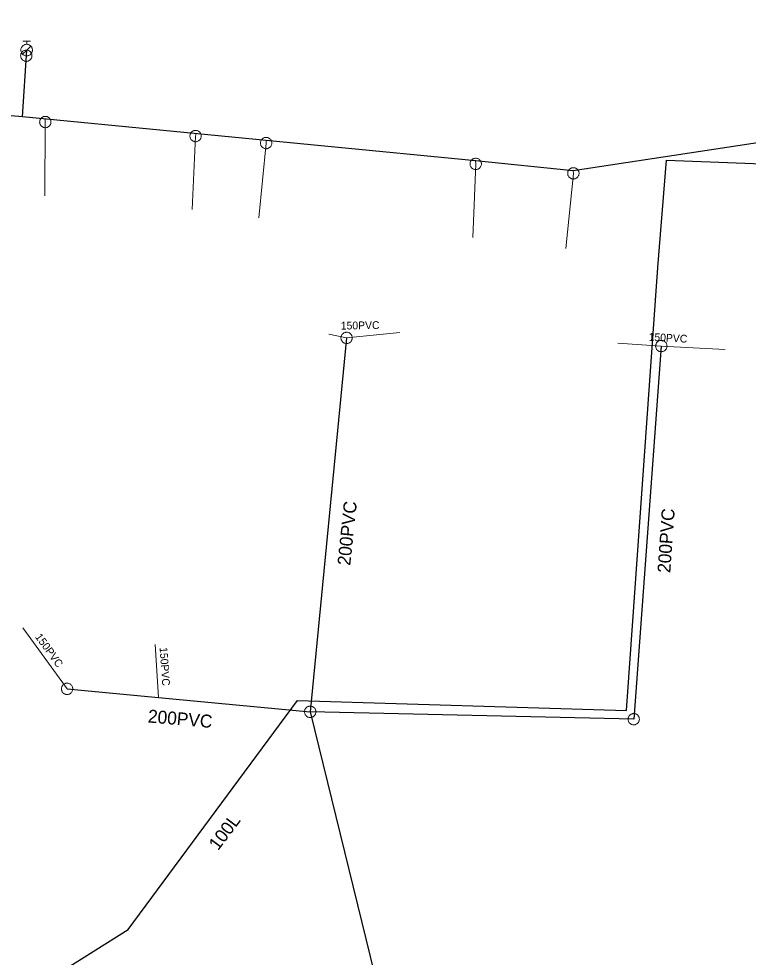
# Model space of a CAD drawing. Extents: x -741806 to -738704, y -1059275 to -1055387.
# Drawn here: x -740724.1 to -740667.8, y -1057649.4 to -1057576.9 of the extents above; entities that cross this region are included whole.
import ezdxf

# ---------------------------------------------------------------- set-up
doc = ezdxf.new("R2010")
doc.units = 0
doc.header["$LTSCALE"] = 0.4
for name, color, linetype, lineweight in [('2', 7, 'Continuous', 25), ('21', 7, 'Continuous', 13), ('3', 7, 'Continuous', 13), ('50', 7, 'Continuous', 13), ('51', 7, 'Continuous', 13), ('52', 7, 'Continuous', 25), ('56', 7, 'Continuous', 13)]:
    doc.layers.add(name, color=color, linetype=linetype, lineweight=lineweight)
doc.layers.add('5', color=7, linetype='Continuous')
doc.layers.add('55', color=7, linetype='Continuous')

msp = doc.modelspace()

# ---------------------------------------------------------------- linework, layer by layer
at = {"layer": '2'}
msp.add_line((-740698.8, -1057601.58), (-740701.609, -1057630.44), dxfattribs=at)
for points in [[(-740702.59, -1057629.575), (-740677.195, -1057630.344), (-740674.756, -1057596.152), (-740674.105, -1057587.855), (-740634.449, -1057589.387), (-740633.142, -1057565.869)], [(-740674.5, -1057602.21), (-740676.629, -1057631.01), (-740701.609, -1057630.44)], [(-740720.379, -1057628.669), (-740713.316, -1057629.345), (-740701.609, -1057630.44)], [(-740723.35, -1057652.071), (-740715.67, -1057647.25), (-740702.59, -1057629.575)], [(-740701.609, -1057630.44), (-740690.68, -1057675.03), (-740701.17, -1057709.36)]]:
    msp.add_lwpolyline(points, dxfattribs=at)
at = {"layer": '21'}
for points in [[(-740722.077, -1057584.688), (-740722.059, -1057584.919), (-740722.101, -1057590.605)], [(-740710.424, -1057585.816), (-740710.46, -1057586), (-740710.73, -1057591.678)], [(-740705.013, -1057586.34), (-740705.01, -1057586.54), (-740705.581, -1057592.321)], [(-740688.844, -1057587.905), (-740688.829, -1057588.149), (-740689.061, -1057593.823)], [(-740681.293, -1057588.681), (-740681.289, -1057588.879), (-740681.875, -1057594.681)]]:
    msp.add_lwpolyline(points, dxfattribs=at)
at = {"layer": '3'}
for points in [[(-740698.371, -1057601.669), (-740698.365, -1057601.624), (-740698.362, -1057601.579), (-740698.365, -1057601.532), (-740698.372, -1057601.488), (-740698.384, -1057601.444), (-740698.401, -1057601.4), (-740698.422, -1057601.36), (-740698.447, -1057601.321), (-740698.476, -1057601.287), (-740698.508, -1057601.254), (-740698.544, -1057601.226), (-740698.583, -1057601.2), (-740698.624, -1057601.18), (-740698.666, -1057601.163), (-740698.711, -1057601.152), (-740698.756, -1057601.145), (-740698.802, -1057601.143), (-740698.847, -1057601.145), (-740698.893, -1057601.153), (-740698.937, -1057601.165), (-740698.979, -1057601.182), (-740699.019, -1057601.202), (-740699.058, -1057601.228), (-740699.094, -1057601.256), (-740699.126, -1057601.289), (-740699.154, -1057601.326), (-740699.179, -1057601.363), (-740699.2, -1057601.405), (-740699.216, -1057601.447), (-740699.228, -1057601.492), (-740699.235, -1057601.537), (-740699.237, -1057601.582), (-740699.235, -1057601.629), (-740699.227, -1057601.674), (-740699.215, -1057601.717), (-740699.199, -1057601.761), (-740699.177, -1057601.801), (-740699.152, -1057601.84), (-740699.123, -1057601.874), (-740699.091, -1057601.907), (-740699.055, -1057601.935), (-740699.017, -1057601.961), (-740698.976, -1057601.982), (-740698.933, -1057601.998), (-740698.889, -1057602.009), (-740698.843, -1057602.016), (-740698.798, -1057602.019), (-740698.752, -1057602.016), (-740698.707, -1057602.008), (-740698.662, -1057601.996), (-740698.62, -1057601.979), (-740698.579, -1057601.959), (-740698.541, -1057601.933), (-740698.505, -1057601.905), (-740698.473, -1057601.871), (-740698.444, -1057601.836), (-740698.42, -1057601.798), (-740698.399, -1057601.756), (-740698.383, -1057601.714), (-740698.371, -1057601.67)], [(-740674.937, -1057602.187), (-740674.936, -1057602.232), (-740674.932, -1057602.277), (-740674.922, -1057602.322), (-740674.908, -1057602.365), (-740674.889, -1057602.407), (-740674.866, -1057602.447), (-740674.839, -1057602.484), (-740674.809, -1057602.519), (-740674.774, -1057602.548), (-740674.738, -1057602.575), (-740674.698, -1057602.598), (-740674.656, -1057602.618), (-740674.612, -1057602.631), (-740674.568, -1057602.641), (-740674.522, -1057602.645), (-740674.476, -1057602.646), (-740674.431, -1057602.64), (-740674.386, -1057602.631), (-740674.342, -1057602.617), (-740674.3, -1057602.598), (-740674.261, -1057602.575), (-740674.225, -1057602.549), (-740674.19, -1057602.517), (-740674.159, -1057602.484), (-740674.132, -1057602.446), (-740674.11, -1057602.406), (-740674.091, -1057602.365), (-740674.077, -1057602.321), (-740674.067, -1057602.276), (-740674.063, -1057602.23), (-740674.063, -1057602.185), (-740674.067, -1057602.14), (-740674.077, -1057602.095), (-740674.092, -1057602.051), (-740674.11, -1057602.01), (-740674.133, -1057601.97), (-740674.16, -1057601.933), (-740674.191, -1057601.898), (-740674.225, -1057601.869), (-740674.261, -1057601.842), (-740674.301, -1057601.819), (-740674.343, -1057601.799), (-740674.387, -1057601.785), (-740674.431, -1057601.776), (-740674.477, -1057601.772), (-740674.523, -1057601.771), (-740674.568, -1057601.776), (-740674.613, -1057601.786), (-740674.657, -1057601.8), (-740674.699, -1057601.819), (-740674.738, -1057601.842), (-740674.775, -1057601.868), (-740674.809, -1057601.9), (-740674.84, -1057601.933), (-740674.867, -1057601.971), (-740674.89, -1057602.011), (-740674.908, -1057602.052), (-740674.922, -1057602.096), (-740674.932, -1057602.141), (-740674.937, -1057602.186)], [(-740720.122, -1057629.023), (-740720.087, -1057628.994), (-740720.055, -1057628.962), (-740720.025, -1057628.926), (-740720.001, -1057628.888), (-740719.98, -1057628.847), (-740719.963, -1057628.804), (-740719.952, -1057628.76), (-740719.944, -1057628.715), (-740719.942, -1057628.669), (-740719.944, -1057628.624), (-740719.951, -1057628.578), (-740719.963, -1057628.534), (-740719.98, -1057628.492), (-740720, -1057628.45), (-740720.025, -1057628.412), (-740720.054, -1057628.376), (-740720.087, -1057628.344), (-740720.122, -1057628.315), (-740720.161, -1057628.29), (-740720.202, -1057628.269), (-740720.244, -1057628.253), (-740720.287, -1057628.242), (-740720.334, -1057628.234), (-740720.379, -1057628.231), (-740720.425, -1057628.234), (-740720.47, -1057628.242), (-740720.514, -1057628.253), (-740720.558, -1057628.27), (-740720.598, -1057628.29), (-740720.636, -1057628.316), (-740720.672, -1057628.344), (-740720.704, -1057628.376), (-740720.733, -1057628.412), (-740720.758, -1057628.451), (-740720.779, -1057628.491), (-740720.796, -1057628.534), (-740720.807, -1057628.578), (-740720.814, -1057628.624), (-740720.816, -1057628.669), (-740720.814, -1057628.714), (-740720.807, -1057628.76), (-740720.796, -1057628.805), (-740720.78, -1057628.847), (-740720.759, -1057628.888), (-740720.733, -1057628.926), (-740720.705, -1057628.962), (-740720.673, -1057628.994), (-740720.637, -1057629.023), (-740720.598, -1057629.048), (-740720.557, -1057629.069), (-740720.514, -1057629.085), (-740720.471, -1057629.097), (-740720.425, -1057629.104), (-740720.38, -1057629.107), (-740720.333, -1057629.104), (-740720.288, -1057629.097), (-740720.245, -1057629.085), (-740720.201, -1057629.069), (-740720.161, -1057629.048), (-740720.122, -1057629.024)], [(-740701.172, -1057630.481), (-740701.171, -1057630.436), (-740701.174, -1057630.39), (-740701.182, -1057630.344), (-740701.194, -1057630.301), (-740701.211, -1057630.258), (-740701.232, -1057630.217), (-740701.258, -1057630.18), (-740701.287, -1057630.144), (-740701.32, -1057630.112), (-740701.355, -1057630.084), (-740701.394, -1057630.059), (-740701.435, -1057630.038), (-740701.478, -1057630.023), (-740701.522, -1057630.011), (-740701.568, -1057630.005), (-740701.614, -1057630.003), (-740701.659, -1057630.006), (-740701.704, -1057630.013), (-740701.749, -1057630.026), (-740701.791, -1057630.043), (-740701.832, -1057630.065), (-740701.869, -1057630.089), (-740701.905, -1057630.119), (-740701.937, -1057630.151), (-740701.966, -1057630.188), (-740701.989, -1057630.227), (-740702.01, -1057630.267), (-740702.026, -1057630.311), (-740702.037, -1057630.355), (-740702.044, -1057630.4), (-740702.046, -1057630.445), (-740702.043, -1057630.491), (-740702.035, -1057630.537), (-740702.022, -1057630.581), (-740702.006, -1057630.623), (-740701.985, -1057630.664), (-740701.959, -1057630.701), (-740701.93, -1057630.737), (-740701.897, -1057630.769), (-740701.862, -1057630.797), (-740701.823, -1057630.822), (-740701.782, -1057630.843), (-740701.739, -1057630.859), (-740701.695, -1057630.87), (-740701.649, -1057630.876), (-740701.603, -1057630.878), (-740701.558, -1057630.876), (-740701.513, -1057630.868), (-740701.469, -1057630.855), (-740701.426, -1057630.838), (-740701.386, -1057630.816), (-740701.347, -1057630.792), (-740701.312, -1057630.762), (-740701.28, -1057630.73), (-740701.252, -1057630.693), (-740701.227, -1057630.654), (-740701.207, -1057630.614), (-740701.191, -1057630.57), (-740701.18, -1057630.526), (-740701.173, -1057630.482)], [(-740676.661, -1057631.446), (-740676.616, -1057631.447), (-740676.571, -1057631.443), (-740676.525, -1057631.434), (-740676.482, -1057631.421), (-740676.44, -1057631.404), (-740676.399, -1057631.381), (-740676.362, -1057631.355), (-740676.326, -1057631.326), (-740676.296, -1057631.292), (-740676.268, -1057631.256), (-740676.244, -1057631.216), (-740676.224, -1057631.175), (-740676.21, -1057631.132), (-740676.199, -1057631.087), (-740676.193, -1057631.042), (-740676.192, -1057630.996), (-740676.196, -1057630.95), (-740676.204, -1057630.906), (-740676.218, -1057630.861), (-740676.236, -1057630.819), (-740676.258, -1057630.779), (-740676.283, -1057630.742), (-740676.314, -1057630.707), (-740676.347, -1057630.675), (-740676.384, -1057630.648), (-740676.423, -1057630.625), (-740676.464, -1057630.605), (-740676.508, -1057630.589), (-740676.552, -1057630.579), (-740676.598, -1057630.574), (-740676.643, -1057630.572), (-740676.688, -1057630.576), (-740676.734, -1057630.585), (-740676.778, -1057630.598), (-740676.819, -1057630.615), (-740676.86, -1057630.637), (-740676.897, -1057630.664), (-740676.933, -1057630.694), (-740676.963, -1057630.727), (-740676.991, -1057630.763), (-740677.015, -1057630.802), (-740677.035, -1057630.844), (-740677.05, -1057630.887), (-740677.06, -1057630.931), (-740677.066, -1057630.977), (-740677.067, -1057631.023), (-740677.064, -1057631.069), (-740677.055, -1057631.113), (-740677.041, -1057631.157), (-740677.023, -1057631.2), (-740677.001, -1057631.24), (-740676.976, -1057631.278), (-740676.945, -1057631.312), (-740676.912, -1057631.343), (-740676.875, -1057631.371), (-740676.836, -1057631.395), (-740676.795, -1057631.414), (-740676.751, -1057631.43), (-740676.707, -1057631.44), (-740676.662, -1057631.446)]]:
    msp.add_lwpolyline(points, dxfattribs=at)
at = {"layer": '50'}
for p, q in [((-740723.808, -1057578.666), (-740723.5, -1057578.666)), ((-740723.5, -1057578.917), (-740723.5, -1057578.666)), ((-740723.193, -1057578.666), (-740723.5, -1057578.666)), ((-740723.5, -1057579.364), (-740723.817, -1057579.681)), ((-740723.5, -1057579.364), (-740723.184, -1057579.052))]:
    msp.add_line(p, q, dxfattribs=at)
msp.add_lwpolyline([(-740723.056, -1057579.368), (-740723.058, -1057579.319), (-740723.063, -1057579.273), (-740723.076, -1057579.227), (-740723.093, -1057579.184), (-740723.112, -1057579.144), (-740723.139, -1057579.103), (-740723.168, -1057579.068), (-740723.201, -1057579.033), (-740723.236, -1057579.003), (-740723.276, -1057578.979), (-740723.317, -1057578.957), (-740723.36, -1057578.938), (-740723.406, -1057578.928), (-740723.452, -1057578.92), (-740723.498, -1057578.917), (-740723.544, -1057578.92), (-740723.589, -1057578.925), (-740723.635, -1057578.938), (-740723.679, -1057578.955), (-740723.722, -1057578.976), (-740723.76, -1057579.001), (-740723.797, -1057579.03), (-740723.83, -1057579.063), (-740723.859, -1057579.098), (-740723.886, -1057579.138), (-740723.908, -1057579.179), (-740723.924, -1057579.222), (-740723.938, -1057579.268), (-740723.943, -1057579.314), (-740723.95, -1057579.36), (-740723.947, -1057579.408), (-740723.939, -1057579.454), (-740723.928, -1057579.497), (-740723.912, -1057579.543), (-740723.89, -1057579.584), (-740723.866, -1057579.624), (-740723.836, -1057579.659), (-740723.804, -1057579.694), (-740723.766, -1057579.724), (-740723.728, -1057579.748), (-740723.685, -1057579.77), (-740723.642, -1057579.786), (-740723.599, -1057579.8), (-740723.55, -1057579.808), (-740723.504, -1057579.811), (-740723.458, -1057579.808), (-740723.412, -1057579.8), (-740723.366, -1057579.789), (-740723.323, -1057579.773), (-740723.28, -1057579.751), (-740723.242, -1057579.727), (-740723.204, -1057579.697), (-740723.172, -1057579.665), (-740723.142, -1057579.63), (-740723.118, -1057579.589), (-740723.094, -1057579.549), (-740723.077, -1057579.505), (-740723.067, -1057579.46), (-740723.059, -1057579.414)], close=True, dxfattribs=at)
at = {"layer": '51'}
for points in [[(-740723.091, -1057579.802), (-740723.093, -1057579.757), (-740723.1, -1057579.712), (-740723.112, -1057579.667), (-740723.128, -1057579.625), (-740723.149, -1057579.584), (-740723.174, -1057579.545), (-740723.203, -1057579.51), (-740723.235, -1057579.477), (-740723.271, -1057579.449), (-740723.309, -1057579.424), (-740723.35, -1057579.403), (-740723.393, -1057579.386), (-740723.437, -1057579.374), (-740723.482, -1057579.367), (-740723.528, -1057579.365), (-740723.574, -1057579.367), (-740723.619, -1057579.374), (-740723.663, -1057579.386), (-740723.706, -1057579.403), (-740723.747, -1057579.424), (-740723.785, -1057579.449), (-740723.821, -1057579.477), (-740723.853, -1057579.51), (-740723.882, -1057579.545), (-740723.907, -1057579.584), (-740723.928, -1057579.625), (-740723.944, -1057579.667), (-740723.956, -1057579.712), (-740723.963, -1057579.757), (-740723.966, -1057579.803), (-740723.963, -1057579.848), (-740723.956, -1057579.893), (-740723.944, -1057579.938), (-740723.928, -1057579.98), (-740723.907, -1057580.021), (-740723.882, -1057580.06), (-740723.853, -1057580.095), (-740723.821, -1057580.128), (-740723.785, -1057580.156), (-740723.747, -1057580.181), (-740723.706, -1057580.202), (-740723.663, -1057580.219), (-740723.619, -1057580.23), (-740723.574, -1057580.238), (-740723.528, -1057580.24), (-740723.482, -1057580.238), (-740723.437, -1057580.23), (-740723.393, -1057580.219), (-740723.35, -1057580.202), (-740723.309, -1057580.181), (-740723.271, -1057580.156), (-740723.235, -1057580.128), (-740723.203, -1057580.095), (-740723.174, -1057580.06), (-740723.149, -1057580.021), (-740723.128, -1057579.98), (-740723.112, -1057579.938), (-740723.1, -1057579.893), (-740723.093, -1057579.848), (-740723.091, -1057579.803)], [(-740721.622, -1057584.919), (-740721.624, -1057584.874), (-740721.631, -1057584.829), (-740721.643, -1057584.784), (-740721.659, -1057584.742), (-740721.68, -1057584.701), (-740721.705, -1057584.662), (-740721.734, -1057584.627), (-740721.766, -1057584.594), (-740721.802, -1057584.566), (-740721.84, -1057584.541), (-740721.881, -1057584.52), (-740721.924, -1057584.503), (-740721.968, -1057584.491), (-740722.013, -1057584.484), (-740722.059, -1057584.482), (-740722.105, -1057584.484), (-740722.15, -1057584.491), (-740722.194, -1057584.503), (-740722.237, -1057584.52), (-740722.278, -1057584.541), (-740722.316, -1057584.566), (-740722.352, -1057584.594), (-740722.384, -1057584.627), (-740722.413, -1057584.662), (-740722.438, -1057584.701), (-740722.459, -1057584.742), (-740722.475, -1057584.784), (-740722.487, -1057584.829), (-740722.494, -1057584.874), (-740722.497, -1057584.92), (-740722.494, -1057584.965), (-740722.487, -1057585.01), (-740722.475, -1057585.055), (-740722.459, -1057585.097), (-740722.438, -1057585.138), (-740722.413, -1057585.177), (-740722.384, -1057585.212), (-740722.352, -1057585.245), (-740722.316, -1057585.273), (-740722.278, -1057585.298), (-740722.237, -1057585.319), (-740722.194, -1057585.336), (-740722.15, -1057585.347), (-740722.105, -1057585.355), (-740722.059, -1057585.357), (-740722.013, -1057585.355), (-740721.968, -1057585.347), (-740721.924, -1057585.336), (-740721.881, -1057585.319), (-740721.84, -1057585.298), (-740721.802, -1057585.273), (-740721.766, -1057585.245), (-740721.734, -1057585.212), (-740721.705, -1057585.177), (-740721.68, -1057585.138), (-740721.659, -1057585.097), (-740721.643, -1057585.055), (-740721.631, -1057585.01), (-740721.624, -1057584.965), (-740721.622, -1057584.92)], [(-740710.022, -1057586), (-740710.024, -1057585.955), (-740710.032, -1057585.91), (-740710.044, -1057585.865), (-740710.059, -1057585.823), (-740710.081, -1057585.782), (-740710.105, -1057585.743), (-740710.135, -1057585.708), (-740710.167, -1057585.675), (-740710.203, -1057585.647), (-740710.24, -1057585.622), (-740710.282, -1057585.601), (-740710.325, -1057585.584), (-740710.369, -1057585.572), (-740710.414, -1057585.565), (-740710.46, -1057585.563), (-740710.505, -1057585.565), (-740710.551, -1057585.572), (-740710.595, -1057585.584), (-740710.637, -1057585.601), (-740710.679, -1057585.622), (-740710.717, -1057585.647), (-740710.752, -1057585.675), (-740710.784, -1057585.708), (-740710.814, -1057585.743), (-740710.838, -1057585.782), (-740710.86, -1057585.823), (-740710.875, -1057585.865), (-740710.887, -1057585.91), (-740710.895, -1057585.955), (-740710.897, -1057586.001), (-740710.895, -1057586.046), (-740710.887, -1057586.091), (-740710.875, -1057586.136), (-740710.86, -1057586.178), (-740710.838, -1057586.219), (-740710.814, -1057586.258), (-740710.784, -1057586.293), (-740710.752, -1057586.326), (-740710.717, -1057586.354), (-740710.679, -1057586.379), (-740710.637, -1057586.4), (-740710.595, -1057586.417), (-740710.551, -1057586.428), (-740710.505, -1057586.436), (-740710.46, -1057586.438), (-740710.414, -1057586.436), (-740710.369, -1057586.428), (-740710.325, -1057586.417), (-740710.282, -1057586.4), (-740710.24, -1057586.379), (-740710.203, -1057586.354), (-740710.167, -1057586.326), (-740710.135, -1057586.293), (-740710.105, -1057586.258), (-740710.081, -1057586.219), (-740710.059, -1057586.178), (-740710.044, -1057586.136), (-740710.032, -1057586.091), (-740710.024, -1057586.046), (-740710.022, -1057586.001)], [(-740704.573, -1057586.54), (-740704.575, -1057586.495), (-740704.582, -1057586.45), (-740704.594, -1057586.405), (-740704.61, -1057586.363), (-740704.631, -1057586.322), (-740704.656, -1057586.283), (-740704.685, -1057586.248), (-740704.717, -1057586.215), (-740704.753, -1057586.187), (-740704.791, -1057586.162), (-740704.832, -1057586.141), (-740704.875, -1057586.124), (-740704.919, -1057586.112), (-740704.964, -1057586.105), (-740705.01, -1057586.103), (-740705.056, -1057586.105), (-740705.101, -1057586.112), (-740705.145, -1057586.124), (-740705.188, -1057586.141), (-740705.229, -1057586.162), (-740705.267, -1057586.187), (-740705.303, -1057586.215), (-740705.335, -1057586.248), (-740705.364, -1057586.283), (-740705.389, -1057586.322), (-740705.41, -1057586.363), (-740705.426, -1057586.405), (-740705.438, -1057586.45), (-740705.445, -1057586.495), (-740705.448, -1057586.541), (-740705.445, -1057586.586), (-740705.438, -1057586.631), (-740705.426, -1057586.676), (-740705.41, -1057586.718), (-740705.389, -1057586.759), (-740705.364, -1057586.798), (-740705.335, -1057586.833), (-740705.303, -1057586.866), (-740705.267, -1057586.894), (-740705.229, -1057586.919), (-740705.188, -1057586.94), (-740705.145, -1057586.957), (-740705.101, -1057586.968), (-740705.056, -1057586.976), (-740705.01, -1057586.978), (-740704.964, -1057586.976), (-740704.919, -1057586.968), (-740704.875, -1057586.957), (-740704.832, -1057586.94), (-740704.791, -1057586.919), (-740704.753, -1057586.894), (-740704.717, -1057586.866), (-740704.685, -1057586.833), (-740704.656, -1057586.798), (-740704.631, -1057586.759), (-740704.61, -1057586.718), (-740704.594, -1057586.676), (-740704.582, -1057586.631), (-740704.575, -1057586.586), (-740704.573, -1057586.541)], [(-740688.392, -1057588.149), (-740688.394, -1057588.104), (-740688.401, -1057588.059), (-740688.413, -1057588.014), (-740688.429, -1057587.972), (-740688.45, -1057587.931), (-740688.475, -1057587.892), (-740688.504, -1057587.857), (-740688.536, -1057587.824), (-740688.572, -1057587.796), (-740688.61, -1057587.771), (-740688.651, -1057587.75), (-740688.694, -1057587.733), (-740688.738, -1057587.721), (-740688.783, -1057587.714), (-740688.829, -1057587.712), (-740688.875, -1057587.714), (-740688.92, -1057587.721), (-740688.964, -1057587.733), (-740689.007, -1057587.75), (-740689.048, -1057587.771), (-740689.086, -1057587.796), (-740689.122, -1057587.824), (-740689.154, -1057587.857), (-740689.183, -1057587.892), (-740689.208, -1057587.931), (-740689.229, -1057587.972), (-740689.245, -1057588.014), (-740689.257, -1057588.059), (-740689.264, -1057588.104), (-740689.267, -1057588.15), (-740689.264, -1057588.195), (-740689.257, -1057588.24), (-740689.245, -1057588.285), (-740689.229, -1057588.327), (-740689.208, -1057588.368), (-740689.183, -1057588.407), (-740689.154, -1057588.442), (-740689.122, -1057588.475), (-740689.086, -1057588.503), (-740689.048, -1057588.528), (-740689.007, -1057588.549), (-740688.964, -1057588.566), (-740688.92, -1057588.577), (-740688.875, -1057588.585), (-740688.829, -1057588.587), (-740688.783, -1057588.585), (-740688.738, -1057588.577), (-740688.694, -1057588.566), (-740688.651, -1057588.549), (-740688.61, -1057588.528), (-740688.572, -1057588.503), (-740688.536, -1057588.475), (-740688.504, -1057588.442), (-740688.475, -1057588.407), (-740688.45, -1057588.368), (-740688.429, -1057588.327), (-740688.413, -1057588.285), (-740688.401, -1057588.24), (-740688.394, -1057588.195), (-740688.392, -1057588.15)], [(-740680.852, -1057588.879), (-740680.853, -1057588.834), (-740680.861, -1057588.789), (-740680.873, -1057588.744), (-740680.889, -1057588.702), (-740680.91, -1057588.661), (-740680.934, -1057588.622), (-740680.964, -1057588.587), (-740680.996, -1057588.554), (-740681.032, -1057588.526), (-740681.07, -1057588.501), (-740681.111, -1057588.48), (-740681.154, -1057588.463), (-740681.198, -1057588.451), (-740681.243, -1057588.444), (-740681.289, -1057588.442), (-740681.335, -1057588.444), (-740681.38, -1057588.451), (-740681.424, -1057588.463), (-740681.467, -1057588.48), (-740681.508, -1057588.501), (-740681.546, -1057588.526), (-740681.581, -1057588.554), (-740681.614, -1057588.587), (-740681.643, -1057588.622), (-740681.668, -1057588.661), (-740681.689, -1057588.702), (-740681.705, -1057588.744), (-740681.717, -1057588.789), (-740681.724, -1057588.834), (-740681.727, -1057588.88), (-740681.724, -1057588.925), (-740681.717, -1057588.97), (-740681.705, -1057589.015), (-740681.689, -1057589.057), (-740681.668, -1057589.098), (-740681.643, -1057589.137), (-740681.614, -1057589.172), (-740681.581, -1057589.205), (-740681.546, -1057589.233), (-740681.508, -1057589.258), (-740681.467, -1057589.279), (-740681.424, -1057589.296), (-740681.38, -1057589.307), (-740681.335, -1057589.315), (-740681.289, -1057589.317), (-740681.243, -1057589.315), (-740681.198, -1057589.307), (-740681.154, -1057589.296), (-740681.111, -1057589.279), (-740681.07, -1057589.258), (-740681.032, -1057589.233), (-740680.996, -1057589.205), (-740680.964, -1057589.172), (-740680.934, -1057589.137), (-740680.91, -1057589.098), (-740680.889, -1057589.057), (-740680.873, -1057589.015), (-740680.861, -1057588.97), (-740680.853, -1057588.925), (-740680.852, -1057588.88)]]:
    msp.add_lwpolyline(points, dxfattribs=at)
at = {"layer": '52'}
msp.add_line((-740723.829, -1057584.519), (-740723.5, -1057579.36), dxfattribs=at)
for points in [[(-740723.829, -1057584.519), (-740724.693, -1057584.43), (-740728.257, -1057583.93), (-740762.811, -1057580.919), (-740766.647, -1057582.333), (-740767.896, -1057583.914), (-740768.258, -1057586.068), (-740768.221, -1057590.793), (-740768.276, -1057593.736), (-740768.169, -1057603.12), (-740768.186, -1057606.262), (-740768.039, -1057615.274), (-740767.925, -1057618.713), (-740767.909, -1057629.21), (-740767.824, -1057631.212), (-740767.817, -1057641.745), (-740767.701, -1057643.739), (-740767.68, -1057653.215)], [(-740606.199, -1057591.97), (-740644.067, -1057587.834), (-740662.486, -1057585.823), (-740681.293, -1057588.681), (-740688.844, -1057587.905), (-740723.829, -1057584.519)]]:
    msp.add_lwpolyline(points, dxfattribs=at)
at = {"layer": '56'}
for p, q in [((-740694.697, -1057601.156), (-740698.8, -1057601.58)), ((-740700.171, -1057601.294), (-740698.8, -1057601.58)), ((-740677.868, -1057601.994), (-740674.5, -1057602.21)), ((-740669.559, -1057602.463), (-740674.5, -1057602.21)), ((-740723.805, -1057623.953), (-740720.379, -1057628.669)), ((-740713.585, -1057625.237), (-740713.316, -1057629.345))]:
    msp.add_line(p, q, dxfattribs=at)

# ---------------------------------------------------------------- texts
at = {"layer": '5'}
for s, rotation, p in [('200PVC', 84, (-740698.519, -1057619.187)), ('200PVC', 86, (-740673.805, -1057619.747)), ('200PVC', 355, (-740714.168, -1057631.258)), ('100L', 53, (-740708.723, -1057641.201))]:
    msp.add_text(s, height=1, rotation=rotation, dxfattribs=at).set_placement(p)
at = {"layer": '55'}
for rotation, p in [(1, (-740699.241, -1057600.94)), (357, (-740675.491, -1057601.796)), (306, (-740722.882, -1057624.66)), (274, (-740713.237, -1057625.473))]:
    msp.add_text('150PVC', height=0.6, rotation=rotation, dxfattribs=at).set_placement(p)

doc.saveas('drawing.dxf')
